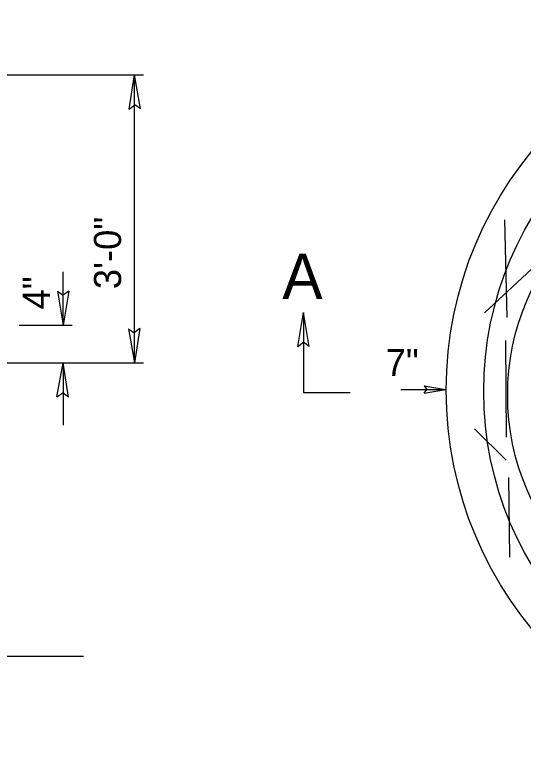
# Model space of a CAD drawing. Extents: x 1.8 to 9.1, y -6 to 4.
# Drawn here: x 3.908 to 5.032, y 2.333 to 3.94 of the extents above; entities that cross this region are included whole.
import ezdxf

# ---------------------------------------------------------------- set-up
doc = ezdxf.new("R2010")
doc.units = 0
for name, color, linetype in [('DETL-DIMS', 7, 'Continuous'), ('DETL-LINE', 7, 'Continuous'), ('DETL-NOTE', 7, 'Continuous'), ('DETL-TITL', 7, 'Continuous')]:
    doc.layers.add(name, color=color, linetype=linetype)

msp = doc.modelspace()

# ---------------------------------------------------------------- linework, layer by layer
at = {"layer": 'DETL-DIMS'}
for p, q in [((3.5193, 3.8069), (4.1922, 3.8069)), ((4.1607, 3.7313), (4.1725, 3.8069)), ((4.1859, 3.7316), (4.1725, 3.8069)), ((4.1725, 3.171), (4.1725, 3.8069)), ((4.1607, 3.7313), (4.1732, 3.7409)), ((4.1859, 3.7316), (4.1732, 3.7409)), ((4.0153, 3.254), (4.0153, 3.372)), ((4.0028, 3.3295), (4.0153, 3.254)), ((4.0028, 3.3295), (4.0153, 3.3201)), ((4.0279, 3.3295), (4.0153, 3.254)), ((4.0279, 3.3295), (4.0153, 3.3201)), ((4.5331, 3.207), (4.5459, 3.2824)), ((4.5582, 3.2069), (4.5459, 3.2824)), ((3.918, 3.254), (4.035, 3.254)), ((4.1592, 3.2463), (4.1725, 3.171)), ((4.1592, 3.2463), (4.1719, 3.237)), ((4.1844, 3.2466), (4.1719, 3.237)), ((4.1844, 3.2466), (4.1725, 3.171)), ((4.5331, 3.207), (4.5457, 3.2164)), ((4.5582, 3.2069), (4.5457, 3.2164)), ((3.8384, 3.171), (4.1922, 3.171)), ((4.0014, 3.0958), (4.0153, 3.171)), ((4.0265, 3.0953), (4.0153, 3.171)), ((4.0153, 3.171), (4.0153, 3.0334)), ((4.8123, 3.12), (4.8594, 3.1122)), ((4.8123, 3.12), (4.8182, 3.1122)), ((4.0014, 3.0958), (4.0141, 3.1049)), ((4.0265, 3.0953), (4.0141, 3.1049)), ((4.7612, 3.1122), (4.8594, 3.1122)), ((4.8123, 3.1043), (4.8594, 3.1122)), ((4.8123, 3.1043), (4.8182, 3.1122))]:
    msp.add_line(p, q, dxfattribs=at)
msp.add_lwpolyline([(4.5459, 3.2824), (4.5459, 3.1055), (4.6489, 3.1055)], dxfattribs=at)
at = {"layer": 'DETL-LINE'}
for p, q in [((4.9897, 3.4868), (4.9946, 3.2712)), ((5.0769, 3.4035), (4.9456, 3.2815)), ((4.9922, 3.22), (4.9938, 3.0072)), ((4.9235, 3.025), (4.9937, 2.956)), ((4.9989, 2.9181), (5.0005, 2.7421))]:
    msp.add_line(p, q, dxfattribs=at)
for centre, radius in [((5.69, 3.1109), 0.829), ((5.6908, 3.108), 0.7469), ((5.531, 3.0998), 0.5342)]:
    msp.add_circle(centre, radius, dxfattribs=at)
at = {"layer": 'DETL-TITL'}
msp.add_line((1.8026, 2.5234), (4.0602, 2.5234), dxfattribs=at)

# ---------------------------------------------------------------- texts
at = {"layer": 'DETL-NOTE'}
for s, p in [('3\'-0"', (4.143, 3.3337)), ('4"', (3.9858, 3.2889))]:
    msp.add_text(s, height=0.05998, rotation=90, dxfattribs=at).set_placement(p)
for s, height, p in [('A', 0.1, (4.499, 3.3119)), ('7"', 0.05998, (4.7273, 3.1417))]:
    msp.add_text(s, height=height, dxfattribs=at).set_placement(p)

doc.saveas('drawing.dxf')
